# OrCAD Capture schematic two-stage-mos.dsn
size A; title: Two-Stage MOS Amplifier
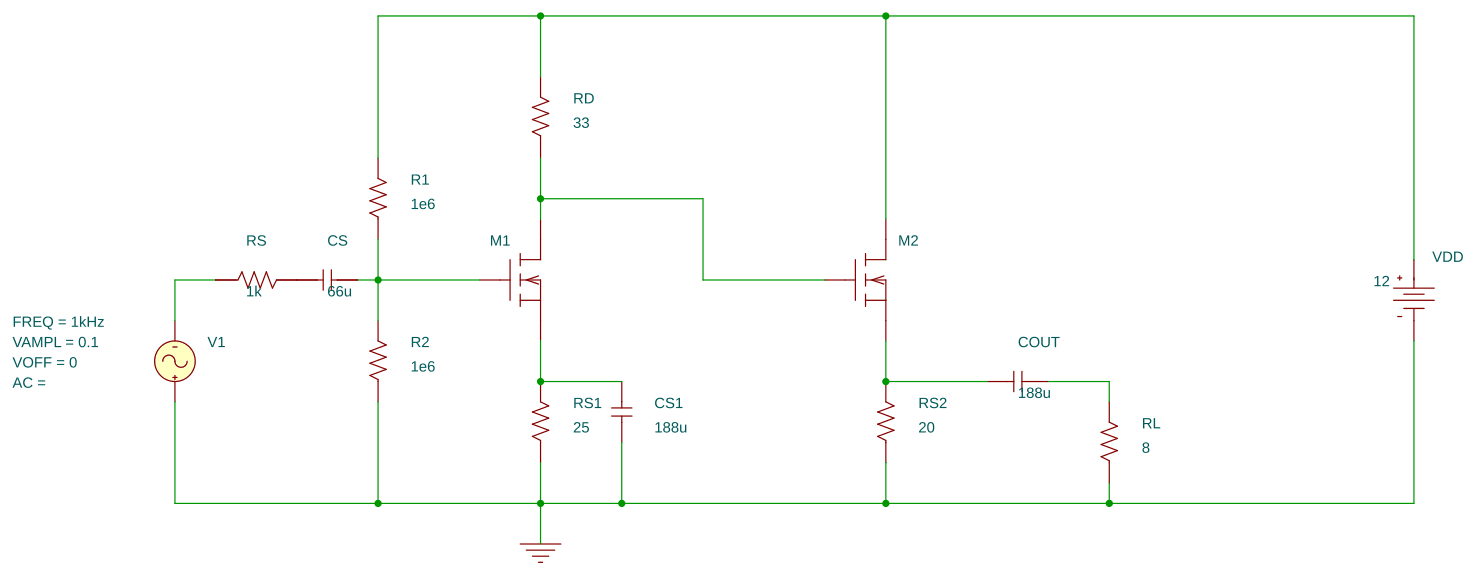
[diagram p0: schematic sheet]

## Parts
COUT  188u  [cap196]
CS  66u  [cap196]
CS1  188u  [cap196]
M1  MbreakN3
M2  MbreakN3
R1  1e6  [AXRC05]
R2  1e6  [AXRC05]
RD  33  [AXRC05]
RL  8  [AXRC05]
RS  1k  [AXRC05]
RS1  25  [AXRC05]
RS2  20  [AXRC05]
V1  VSIN
VDD  VDC

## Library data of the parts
COUT CS CS1 = C
M1 M2 = MbreakN3
R1 R2 RD RL RS RS1 RS2 = R
V1 = VSIN: FREQ: 1kHz; VAMPL: 0.1; VOFF: 0
VDD = VDC: DC: 12

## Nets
0: CS1.1 R2.1 RL.1 RS1.1 RS2.1 V1.1(+) VDD.1(-)
N17004: M2.2(d) R1.2 RD.2 VDD.0(+)
N17052: M1.2(d) M2.1(g) RD.1
N17080: CS.2 M1.1(g) R1.1 R2.2
N17152: RS.1 V1.2(-)
N17222: CS1.2 M1.0(s) RS1.2
N18078: COUT.2 RL.2
N24086: COUT.1 M2.0(s) RS2.2
N26933: CS.1 RS.2
